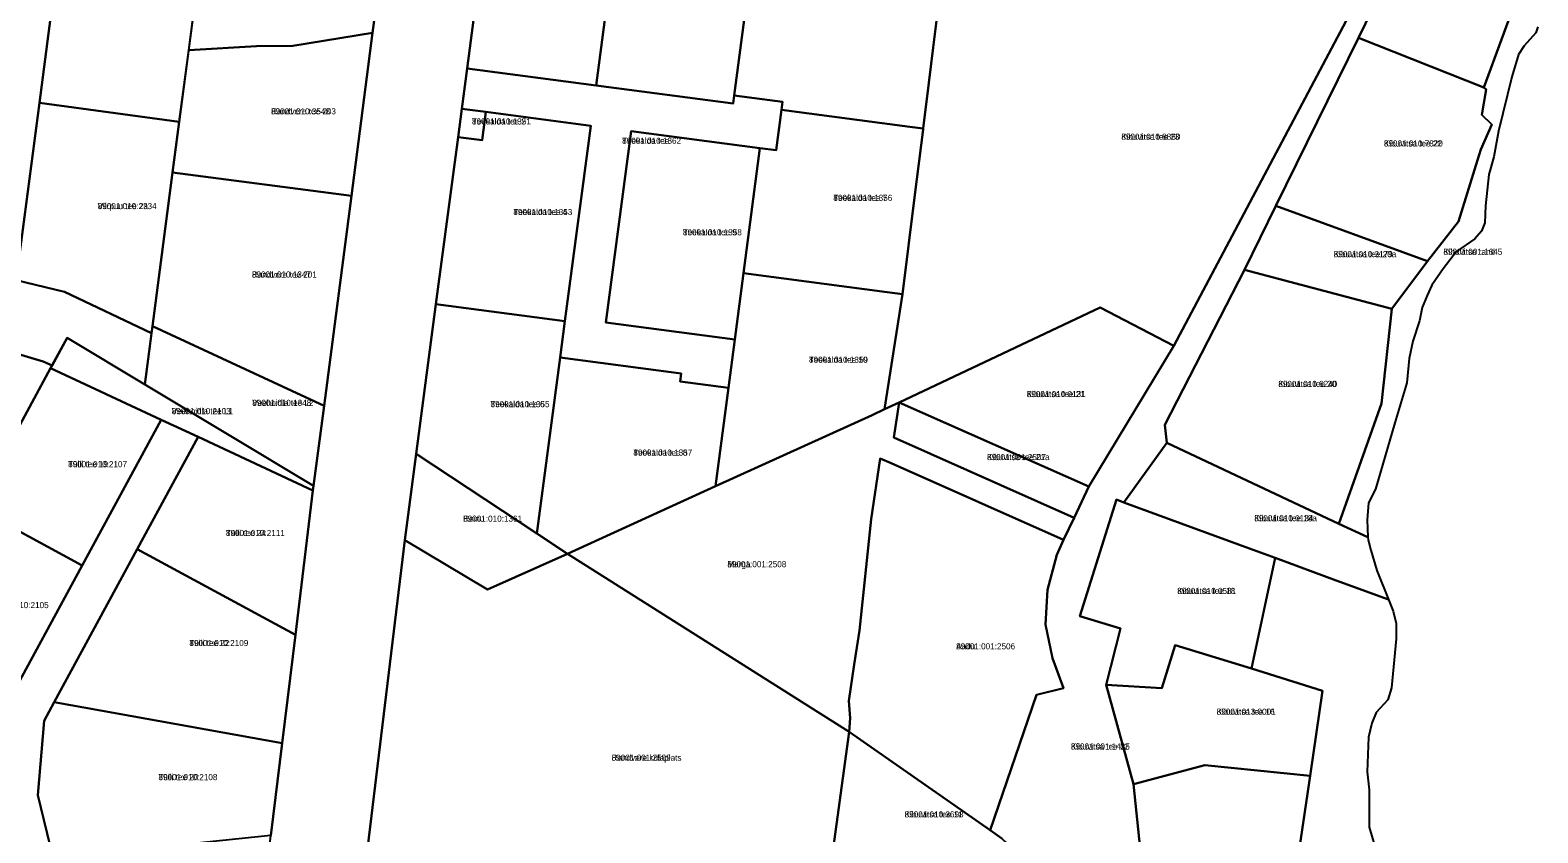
# Model space of a CAD drawing. Extents: x 526849 to 562296, y 6591741 to 6618546.
# Drawn here: x 551215.3 to 551586.1, y 6596928.8 to 6597126.2 of the extents above; entities that cross this region are included whole.
import ezdxf

# ---------------------------------------------------------------- set-up
doc = ezdxf.new("R2010")
doc.units = 0
for name, color, linetype in [('L_AADRESS', 7, 'Continuous'), ('PIIR', 7, 'Continuous'), ('TUNNUS', 7, 'Continuous')]:
    doc.layers.add(name, color=color, linetype=linetype)

msp = doc.modelspace()

# ---------------------------------------------------------------- linework, layer by layer
at = {"layer": 'PIIR'}
for points in [[(551235.47, 6596628.55), (551239.4, 6596658.47), (551243.32, 6596688.28), (551247.22, 6596718.02), (551251.12, 6596747.71), (551255.03, 6596777.46), (551258.94, 6596807.25), (551262.85, 6596837.01), (551267.73, 6596874.18), (551269.99, 6596891.35), (551274.49, 6596928.19), (551277.26, 6596950.92), (551280.5, 6596977.49), (551284.83, 6597013.02), (551284.98, 6597014.21), (551287.55, 6597033.88), (551294.29, 6597085.5), (551299.5, 6597125.57), (551301.33, 6597139.49), (551302.2, 6597146.43), (551302.76, 6597150.44), (551305.84, 6597174.43), (551327.65, 6597350)], [(551348.98, 6597326.82), (551346.35, 6597305.43), (551343.67, 6597283.66), (551340.89, 6597260.98), (551338.21, 6597239.19), (551335.55, 6597217.58), (551332.79, 6597195.11), (551329.65, 6597169.57), (551329.26, 6597166.39), (551329, 6597164.4), (551322.72, 6597116.82), (551321.42, 6597106.9), (551320.5, 6597099.96), (551315.08, 6597058.82), (551310.23, 6597022.05), (551307.4, 6597000.81), (551294.29, 6596892.32)], [(551550.49, 6597141.7), (551542.01, 6597124.37), (551521.69, 6597083.07), (551513.93, 6597067.33), (551494.34, 6597029.15), (551494.84, 6597024.73), (551484.24, 6597010.09), (551482.5, 6597010.77), (551473.49, 6596982.08), (551483.43, 6596979.11), (551479.92, 6596965.26), (551486.64, 6596940.8), (551489.94, 6596909.14)], [(551454.31, 6596927.43), (551451.43, 6596929.46), (551462.79, 6596962.73), (551469.44, 6596964.43), (551466.73, 6596971.8), (551465.02, 6596980.07), (551465.53, 6596988.62), (551467.78, 6596997.23), (551469.48, 6597000.86), (551472.06, 6597006.31), (551475.69, 6597013.97), (551496.61, 6597048.57), (551541.88, 6597134.03)], [(551586.12, 6597127.06), (551585.59, 6597125.58), (551582.73, 6597122.41), (551581.36, 6597120.29), (551579.69, 6597114.75), (551576.46, 6597101.41), (551575.33, 6597095.1), (551574.07, 6597090.74), (551573.21, 6597083.07), (551573.08, 6597078.84), (551572.28, 6597076.84), (551570.63, 6597074.92), (551566.07, 6597071.79), (551562.82, 6597067.5), (551560.06, 6597063.49), (551558.87, 6597060.97), (551557.66, 6597058.04), (551557.01, 6597054.79), (551555.33, 6597049.78), (551554.43, 6597045.5), (551553.88, 6597039.47), (551550.91, 6597029.7), (551546.22, 6597013.32), (551544.5, 6597010.01), (551544.11, 6597005.78), (551544.34, 6597001.53), (551537.2, 6597004.85), (551547.63, 6597034.42), (551550.19, 6597057.73), (551558.97, 6597069.45), (551566.59, 6597079.14), (551571.28, 6597094.26), (551572.1, 6597096.9), (551574.82, 6597103.07), (551572.31, 6597105.42), (551573.38, 6597111.63), (551572.83, 6597112.16), (551581.53, 6597135.8)], [(551208.92, 6596959.33), (551228.04, 6596994.55), (551247.49, 6597030.41), (551256.57, 6597026.18), (551241.6, 6596998.59), (551221.17, 6596960.94), (551218.71, 6596956.4), (551217.18, 6596938.11), (551220.88, 6596922.62), (551230.6, 6596881.94), (551220.92, 6596879.63), (551214.94, 6596904.47)], [(551524.84, 6596907.46), (551530.15, 6596942.87), (551533.15, 6596963.74), (551515.66, 6596969.27), (551521.47, 6596996.44), (551536.54, 6596990.91), (551549.39, 6596986.2), (551550.54, 6596983.34), (551551.25, 6596980.32), (551551.29, 6596976.5), (551550.12, 6596964.48), (551549.18, 6596961.51), (551546.35, 6596958.42), (551545.3, 6596955.77), (551544.5, 6596952.33), (551544.11, 6596943.86), (551544.63, 6596939.37), (551544.63, 6596930.24), (551548.93, 6596915.78)]]:
    msp.add_lwpolyline(points, dxfattribs=at)
for points in [[(551098.85, 6597242.74), (551107.45, 6597232.01), (551099.97, 6597174.72), (551139.39, 6597167.88), (551178.8, 6597161.04), (551218.21, 6597154.19), (551223.39, 6597153.29), (551217.52, 6597108.33), (551211.83, 6597064.74), (551202.05, 6597067.07), (551207.61, 6597109.65), (551212.24, 6597145.09), (551177.5, 6597151.12), (551138.09, 6597157.96), (551098.68, 6597164.79), (551093.47, 6597124.92), (551087.55, 6597079.6), (551077.62, 6597080.68), (551084.05, 6597129.73), (551090.17, 6597176.42), (551096.2, 6597222.45)], [(551329.26, 6597166.39), (551329.56, 6597166.15), (551360.82, 6597160.89), (551360.46, 6597158.17), (551354.45, 6597112.63), (551322.72, 6597116.82), (551329, 6597164.4)], [(551360.46, 6597158.17), (551360.82, 6597160.89), (551371.25, 6597159.13), (551375.83, 6597158.35), (551380.6, 6597157.5), (551394.34, 6597155.05), (551393.91, 6597151.78), (551388.42, 6597110.17), (551388.16, 6597108.19), (551354.45, 6597112.63)], [(551223.39, 6597153.29), (551257.62, 6597147.36), (551251.91, 6597103.73), (551217.52, 6597108.33)], [(551388.42, 6597110.17), (551393.91, 6597151.78), (551394.34, 6597155.05), (551406.13, 6597152.99), (551412.6, 6597151.79), (551432.2, 6597147.96), (551435.55, 6597147.31), (551440.48, 6597147.01), (551439.3, 6597137.13), (551437.39, 6597121.98), (551436.3, 6597113.26), (551434.91, 6597102.03), (551431.62, 6597102.46), (551400.06, 6597106.62), (551400.32, 6597108.6)], [(551270.9, 6597122.3), (551254.25, 6597121.34), (551257.62, 6597147.36), (551258.22, 6597151.64), (551295.17, 6597151.44), (551302.76, 6597150.44), (551302.2, 6597146.43), (551296.29, 6597147.26), (551295.39, 6597140.28), (551301.33, 6597139.49), (551299.5, 6597125.57), (551279.83, 6597122.37)], [(551496.61, 6597048.57), (551478.42, 6597058), (551429.04, 6597034.68), (551425.43, 6597032.99), (551429.86, 6597061.34), (551432.87, 6597085.7), (551434.88, 6597101.82), (551434.91, 6597102.03), (551436.3, 6597113.26), (551437.39, 6597121.98), (551439.3, 6597137.13), (551440.48, 6597147.01), (551443.55, 6597146.47), (551444.57, 6597150.01), (551459.68, 6597147.46), (551485.2, 6597143.02), (551510.96, 6597138.68), (551511.44, 6597139.1), (551541.88, 6597134.03)], [(551581.53, 6597135.8), (551572.83, 6597112.16), (551542.01, 6597124.37), (551550.49, 6597141.7)], [(551254.25, 6597121.34), (551270.9, 6597122.3), (551279.83, 6597122.37), (551299.5, 6597125.57), (551294.29, 6597085.5), (551250.29, 6597091.24), (551251.91, 6597103.73)], [(551521.69, 6597083.07), (551542.01, 6597124.37), (551572.83, 6597112.16), (551573.38, 6597111.63), (551572.31, 6597105.42), (551574.82, 6597103.07), (551572.1, 6597096.9), (551571.28, 6597094.26), (551566.59, 6597079.14), (551558.97, 6597069.45)], [(551322.72, 6597116.82), (551354.45, 6597112.63), (551388.16, 6597108.19), (551388.42, 6597110.17), (551400.32, 6597108.6), (551400.06, 6597106.62), (551398.75, 6597096.71), (551394.78, 6597097.23), (551363.06, 6597101.41), (551356.85, 6597054.32), (551388.57, 6597050.14), (551387, 6597038.24), (551375.11, 6597039.81), (551375.37, 6597041.79), (551345.63, 6597045.71), (551346.8, 6597054.64), (551353.14, 6597102.72), (551327.37, 6597106.12), (551321.42, 6597106.9)], [(551217.52, 6597108.33), (551251.91, 6597103.73), (551250.29, 6597091.24), (551245.36, 6597053.45), (551245.13, 6597051.75), (551223.68, 6597061.91), (551211.83, 6597064.74)], [(551327.37, 6597106.12), (551353.14, 6597102.72), (551346.8, 6597054.64), (551315.08, 6597058.82), (551320.5, 6597099.96), (551326.45, 6597099.18)], [(551321.42, 6597106.9), (551327.37, 6597106.12), (551326.45, 6597099.18), (551320.5, 6597099.96)], [(551400.06, 6597106.62), (551431.62, 6597102.46), (551434.91, 6597102.03), (551434.88, 6597101.82), (551432.87, 6597085.7), (551429.86, 6597061.34), (551426.03, 6597061.84), (551390.73, 6597066.5), (551394.78, 6597097.23), (551398.75, 6597096.71)], [(551363.06, 6597101.41), (551394.78, 6597097.23), (551390.73, 6597066.5), (551388.57, 6597050.14), (551356.85, 6597054.32)], [(551250.29, 6597091.24), (551294.29, 6597085.5), (551287.55, 6597033.88), (551245.36, 6597053.45)], [(551026.24, 6597086.3), (551077.62, 6597080.68), (551087.55, 6597079.6), (551127.29, 6597075.25), (551167.03, 6597070.91), (551202.05, 6597067.07), (551211.83, 6597064.74), (551223.68, 6597061.91), (551245.13, 6597051.75), (551243.48, 6597039.09), (551224.33, 6597050.57), (551220.63, 6597043.76), (551218.47, 6597044.78), (551211.58, 6597046.79), (551209.25, 6597047.47), (551183.91, 6597050.13), (551173.15, 6597051.27), (551120, 6597056.89), (551092.81, 6597059.76), (551022.57, 6597067.17), (551024.69, 6597078.2)], [(551521.69, 6597083.07), (551558.97, 6597069.45), (551550.19, 6597057.73), (551513.93, 6597067.33)], [(551550.19, 6597057.73), (551547.63, 6597034.42), (551537.2, 6597004.85), (551494.84, 6597024.73), (551494.34, 6597029.15), (551513.93, 6597067.33)], [(551390.73, 6597066.5), (551426.03, 6597061.84), (551429.86, 6597061.34), (551425.43, 6597032.99), (551422.39, 6597031.58), (551383.83, 6597014.06), (551387, 6597038.24), (551388.57, 6597050.14)], [(551315.08, 6597058.82), (551346.8, 6597054.64), (551345.63, 6597045.71), (551339.92, 6597002.43), (551310.23, 6597022.05)], [(551478.42, 6597058), (551496.61, 6597048.57), (551475.69, 6597013.97), (551429.04, 6597034.68)], [(551245.36, 6597053.45), (551287.55, 6597033.88), (551284.98, 6597014.21), (551243.48, 6597039.09)], [(551183.91, 6597050.13), (551209.25, 6597047.47), (551211.58, 6597046.79), (551218.47, 6597044.78), (551220.63, 6597043.76), (551220.27, 6597043.08), (551201.69, 6597008.85), (551182.58, 6596973.62), (551178.27, 6596975.86), (551151.24, 6596989.92), (551167.93, 6597020.68)], [(551224.33, 6597050.57), (551243.48, 6597039.09), (551284.98, 6597014.21), (551284.83, 6597013.02), (551256.57, 6597026.18), (551247.49, 6597030.41), (551220.27, 6597043.08)], [(551345.63, 6597045.71), (551375.37, 6597041.79), (551375.11, 6597039.81), (551387, 6597038.24), (551383.83, 6597014.06), (551347.4, 6596997.48), (551339.92, 6597002.43)], [(551220.27, 6597043.08), (551247.49, 6597030.41), (551228.04, 6596994.55), (551201.69, 6597008.85)], [(551416.73, 6596953.63), (551347.4, 6596997.48), (551383.83, 6597014.06), (551422.39, 6597031.58), (551425.43, 6597032.99), (551429.04, 6597034.68), (551427.74, 6597026.08), (551472.06, 6597006.31), (551469.48, 6597000.86), (551427.04, 6597019.73), (551424.38, 6597020.91), (551422.09, 6597005.95), (551419.26, 6596978.59), (551417.98, 6596970.25), (551416.6, 6596961.31), (551416.97, 6596957.05)], [(551427.74, 6597026.08), (551429.04, 6597034.68), (551475.69, 6597013.97), (551472.06, 6597006.31)], [(551256.57, 6597026.18), (551284.83, 6597013.02), (551280.5, 6596977.49), (551241.6, 6596998.59)], [(551494.84, 6597024.73), (551537.2, 6597004.85), (551544.34, 6597001.53), (551544.37, 6597000.88), (551545.03, 6596998.37), (551546.49, 6596993.34), (551549.39, 6596986.2), (551536.54, 6596990.91), (551521.47, 6596996.44), (551518.76, 6596997.43), (551512.51, 6596999.72), (551484.24, 6597010.09)], [(551310.23, 6597022.05), (551339.92, 6597002.43), (551347.4, 6596997.48), (551327.74, 6596988.64), (551307.4, 6597000.81)], [(551424.38, 6597020.91), (551427.04, 6597019.73), (551469.48, 6597000.86), (551467.78, 6596997.23), (551465.53, 6596988.62), (551465.02, 6596980.07), (551466.73, 6596971.8), (551469.44, 6596964.43), (551462.79, 6596962.73), (551451.43, 6596929.46), (551416.73, 6596953.63), (551416.97, 6596957.05), (551416.6, 6596961.31), (551417.98, 6596970.25), (551419.26, 6596978.59), (551422.09, 6597005.95)], [(551201.69, 6597008.85), (551228.04, 6596994.55), (551208.92, 6596959.33), (551182.58, 6596973.62)], [(551484.24, 6597010.09), (551512.51, 6596999.72), (551518.76, 6596997.43), (551521.47, 6596996.44), (551515.66, 6596969.27), (551496.94, 6596974.97), (551493.63, 6596964.39), (551479.92, 6596965.26), (551483.43, 6596979.11), (551473.49, 6596982.08), (551482.5, 6597010.77)], [(551294.29, 6596892.32), (551307.4, 6597000.81), (551327.74, 6596988.64), (551347.4, 6596997.48), (551416.73, 6596953.63), (551412.02, 6596919.51)], [(551241.6, 6596998.59), (551280.5, 6596977.49), (551277.26, 6596950.92), (551221.17, 6596960.94)], [(551479.92, 6596965.26), (551493.63, 6596964.39), (551496.94, 6596974.97), (551515.66, 6596969.27), (551533.15, 6596963.74), (551530.15, 6596942.87), (551504.24, 6596945.49), (551486.64, 6596940.8)], [(551221.17, 6596960.94), (551277.26, 6596950.92), (551274.49, 6596928.19), (551220.88, 6596922.62), (551217.18, 6596938.11), (551218.71, 6596956.4)], [(551416.73, 6596953.63), (551451.43, 6596929.46), (551454.31, 6596927.43), (551471.18, 6596911.61), (551447.6, 6596912.21), (551411.13, 6596913.07), (551412.02, 6596919.51)], [(551524.84, 6596907.46), (551489.94, 6596909.14), (551486.64, 6596940.8), (551504.24, 6596945.49), (551530.15, 6596942.87)]]:
    msp.add_lwpolyline(points, close=True, dxfattribs=at)

# ---------------------------------------------------------------- texts
at = {"layer": 'L_AADRESS'}
for s, p in [('Randvere tee 203', (551274.52, 6597105.54)), ('Teekalda tee 2', (551323.93, 6597103.04)), ('Kibuvitsa tee 23', (551483.66, 6597099.29)), ('Teekalda tee', (551360.87, 6597098.29)), ('Kibuvitsa tee 22', (551548.25, 6597097.63)), ('Teekalda tee 7', (551412.82, 6597084.26)), ('Viirpuu tee 2a', (551231.87, 6597082.22)), ('Teekalda tee 4', (551334.11, 6597080.77)), ('Teekalda tee 9', (551375.82, 6597075.78)), ('Kibuvitsa tee 20a', (551535.91, 6597070.4)), ('Kibuvitsa rand', (551562.88, 6597070.99)), ('Randvere tee 201', (551269.82, 6597065.4)), ('Teekalda tee 10', (551406.84, 6597044.44)), ('Kibuvitsa tee 20', (551522.27, 6597038.49)), ('Veehoidla tee L2', (551269.9, 6597033.83)), ('Teekalda tee 6', (551328.51, 6597033.51)), ('Kibuvitsa tee 21', (551460.4, 6597035.99)), ('Veehoidla tee L1', (551250.08, 6597031.79)), ('Teekalda tee 8', (551363.63, 6597021.6)), ('Tülli tee 19', (551224.59, 6597018.75)), ('Kibuvitsa tee 21a', (551450.63, 6597020.49)), ('Reinu', (551321.76, 6597005.35)), ('Kibuvitsa tee 18a', (551516.37, 6597005.46)), ('Tülli tee 24', (551263.41, 6597001.83)), ('Marga', (551386.76, 6596994.15)), ('Kibuvitsa tee 18', (551497.4, 6596987.58)), ('Tülli tee 22', (551254.42, 6596974.76)), ('Aadu', (551443.04, 6596973.96)), ('Kibuvitsa tee 16', (551507.13, 6596957.88)), ('Kibuvitsa tee L2', (551471.26, 6596949.32)), ('Randvere külaplats', (551358.3, 6596946.57)), ('Tülli tee 20', (551246.82, 6596941.78)), ('Kibuvitsa tee 11', (551430.36, 6596932.62))]:
    msp.add_text(s, height=1.5, dxfattribs=at).set_placement(p)
at = {"layer": 'TUNNUS'}
for s, p in [('89001:010:3548', (551274.52, 6597105.54)), ('89001:010:1351', (551323.93, 6597103.04)), ('89001:010:8860', (551483.66, 6597099.29)), ('89001:010:1362', (551360.87, 6597098.29)), ('89001:010:7820', (551548.25, 6597097.63)), ('89001:010:1356', (551412.82, 6597084.26)), ('89001:010:2334', (551231.87, 6597082.22)), ('89001:010:1353', (551334.11, 6597080.77)), ('89001:010:1358', (551375.82, 6597075.78)), ('89001:010:3179', (551535.91, 6597070.4)), ('89001:001:1645', (551562.88, 6597070.99)), ('89001:010:1347', (551269.82, 6597065.4)), ('89001:010:1359', (551406.84, 6597044.44)), ('89001:010:6240', (551522.27, 6597038.49)), ('89001:010:1348', (551269.9, 6597033.83)), ('89001:010:1355', (551328.51, 6597033.51)), ('89001:010:0131', (551460.4, 6597035.99)), ('89001:010:2103', (551250.08, 6597031.79)), ('89001:010:1357', (551363.63, 6597021.6)), ('89001:010:2107', (551224.59, 6597018.75)), ('89001:001:2507', (551450.63, 6597020.49)), ('89001:010:1361', (551321.76, 6597005.35)), ('89001:010:0134', (551516.37, 6597005.46)), ('89001:010:2111', (551263.41, 6597001.83)), ('89001:001:2508', (551386.76, 6596994.15)), ('89001:010:0581', (551497.4, 6596987.58)), ('89001:010:2105', (551205.31, 6596984.09)), ('89001:010:2109', (551254.42, 6596974.76)), ('89001:001:2506', (551443.04, 6596973.96)), ('89001:013:0001', (551507.13, 6596957.88)), ('89001:001:1435', (551471.26, 6596949.32)), ('89001:001:2509', (551358.3, 6596946.57)), ('89001:010:2108', (551246.82, 6596941.78)), ('89001:010:3698', (551430.36, 6596932.62))]:
    msp.add_text(s, height=1.5, dxfattribs=at).set_placement(p)

doc.saveas('drawing.dxf')
